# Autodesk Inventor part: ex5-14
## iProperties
Created: 2006-03
Part Number: ex5-14
Document SubType Name: Modeling
Designer: Elise Moss
Author: Elise Moss
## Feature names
1. Extrusion1
2. Hole1
3. Shell1
4. Chamfer1
